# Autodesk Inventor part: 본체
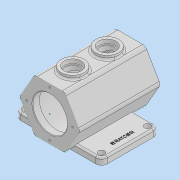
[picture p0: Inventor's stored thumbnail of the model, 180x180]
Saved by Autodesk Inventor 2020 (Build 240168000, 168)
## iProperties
Created: 2021-06
Part Number: 본체
Material: 일반
Document SubType Name: Modeling
Designer: MIRAE
Density: 1 g/cm^3
Appearance: 기본값
Author: MIRAE
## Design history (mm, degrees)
sketch "스케치1" dims "d1" = 105
  geometry: L1 (-26.25, -45.466)-(-52.5, 0); L2 (-52.5, 0)-(-26.25, 45.466); L3 (-26.25, 45.466)-(26.25, 45.466); L4 (26.25, 45.466)-(52.5, 0); L5 (52.5, 0)-(26.25, -45.466); L6 (26.25, -45.466)-(-26.25, -45.466); 3 further points
  constraints: 12 end point, 2 coincident, 1 horizontal, 16 other
extrude "돌출1" new body sketch "스케치1" stored distance "d2" = 140; taper "d3" = 0 deg
sketch "스케치2"
  geometry: L1 (26.25, -45.466)-(52.5, 0) reference; L2 (52.5, 0)-(26.25, 45.466) reference; L3 (26.25, 45.466)-(-26.25, 45.466) reference; L4 (-26.25, 45.466)-(-52.5, 0) reference; L5 (-52.5, 0)-(-26.25, -45.466) reference; L6 (-26.25, -45.466)-(26.25, -45.466) reference; 1 further point
sketch "스케치3"
  geometry: L1 (70, 0)-(70, -45.466) reference; L2 (70, 0)-(70, 30); L3 (70, 45.466)-(70, 0) reference; L4 (70, 30)-(58, 30); L5 (58, 30)-(58, 37.5); L6 (58, 37.5)-(-58, 37.5); L7 (-58, 37.5)-(-58, 30); L8 (-58, 30)-(-70, 30); L9 (-70, 0)-(-70, 45.466) reference; L10 (-70, 30)-(-70, 0); L11 (70, 0)-(-70, 0) reference; L12 (-70, 0)-(70, 0)
  constraints: 16 end point, 4 perpendicular, 3 point on line, 1 collinear, 1 parallel
  dimensions: "d12" = 30 distance of L1.start L2.end; "d13" = 12 distance of L2.end L4.end; "d14" = 37.5 distance between parallel lines of L11 L6; "d15" = 12 distance of L7.end L8.end
revolve "회전2" sketch "스케치3" stored, may be unused: angle "d16" = 90 deg
node "작업 평면2"
sketch "스케치7"
  geometry: L1 (26.25, -70)-(-26.25, -70) reference; C1 r 20 at (0, -30); 1 further point
  constraints: 1 centre point
  dimensions: "d38" = 40 diameter of C1; "d39" = 40 distance from line of L1 C1.centre; "d40" = 0 horizontal distance of point (0, 0) C1.centre
extrude "돌출3" join sketch "스케치7" stored distance "d41" = 10; taper "d42" = 0 deg
sketch "스케치8"
  geometry: C1 r 20 at (0, 0) reference; 2 further points
  constraints: 1 coincident
hole "구멍3" sketch "스케치8" at (0, 0) diameter "d43" = 25; stored, may be unused: countersink angle "d47" = 90 deg, drill point angle "d49" = 0 deg; dims "d44" = 10, "d45" = 30, "d46" = 8, "d48" = 25
node "작업 평면3"
node "작업 평면4"
sketch "스케치9"
  geometry: L1 (52.5, -140)-(52.5, 0) reference; L2 (0, 0)-(52.5, 0) reference; L3 (0, -140)-(0, 0) reference; L4 (52.5, -140)-(0, -140) reference; 1 further point
sketch "스케치10"
  geometry: L1 (-75, 15)-(75, 15); L2 (75, 15)-(75, -85); L3 (75, -85)-(-75, -85); L4 (-75, -85)-(-75, 15); L5 (-52.5, 40)-(-26.25, 40) reference; L6 (-26.25, -100)-(-52.5, -100) reference; 1 further point
  constraints: 8 end point, 2 parallel, 1 horizontal, 1 perpendicular
  dimensions: "d55" = 150 distance of L1.start L1.end; "d56" = 75 distance from line of point (0, -30) L4; "d82" = 25 distance between parallel lines of L1 L5; "d83" = 15 distance between parallel lines of L6 L3
extrude "돌출4" join sketch "스케치10" distance "d59" = 12; taper "d60" = 0 deg
fillet "모깎기1" dims "d73" = 10
sketch "스케치12"
  geometry: C1 r 5.5 at (65, 5); C2 r 5.5 at (65, -75); C3 r 5.5 at (-65, -75); C4 r 5.5 at (-65, 5); A1 r 10 centre (65, 5) between (75, 5) and (65, 15) reference; A2 r 10 centre (65, -75) between (65, -85) and (75, -75) reference; A3 r 10 centre (-65, -75) between (-75, -75) and (-65, -85) reference; A4 r 10 centre (-65, 5) between (-65, 15) and (-75, 5) reference; 1 further point
  constraints: 4 centre point, 4 coincident
  dimensions: "d74" = 11 diameter of C1; "d75" = 11 diameter of C2; "d76" = 11 diameter of C3; "d77" = 11 diameter of C4
extrude "돌출5" cut sketch "스케치12" distance "d78" = 12; taper "d79" = 0 deg
fillet "모깎기2" dims "d80" = 8
sketch "스케치13"
  geometry: L1 (75, -75)-(75, 5) reference; L2 (65, 15)-(30.387, 15) reference; 2 further points
  constraints: 1 other
  dimensions: "d84" = 14 distance from line of point (61, -35) L1; "d85" = 50 distance from line of L2 point (61, -35)
fillet "모깎기3" dims "d86" = 3
fillet "모깎기4" dims "d87" = 5
feature "엠보싱1" dims "d1" = 105, "d88" = 0.5, "d89" = 0
sketch "스케치14" dims "d92" = 80
  geometry: L1 (0, 0)-(50.358, -50.358); L2 (0, 0)-(0, -63.813); C1 r 30 at (0, 0) reference; 2 further points
  constraints: 4 end point, 1 coincident, 1 point on line, 1 vertical, 3 other
  dimensions: "d91" = 45 deg angle of L1 L2
hole "구멍5" sketch "스케치14" at (28.284, -28.284) diameter "d93" = 3.242; stored, may be unused: countersink angle "d97" = 90 deg, drill point angle "d99" = 118 deg; dims "d94" = 8, "d95" = 30, "d96" = 8, "d98" = 10
sketch "스케치15" dims "d103" = 80
  geometry: L1 (0, 0)-(0, 90.933); C1 r 30 at (0, 0) reference; C2 r 30 at (0, 0) reference; 2 further points
  constraints: 2 end point, 1 coincident, 1 point on line, 1 vertical, 1 vertical alignment, 2 other
hole "구멍6" sketch "스케치15" at (0, 40) diameter "d104" = 3.242; stored, may be unused: countersink angle "d108" = 90 deg, drill point angle "d110" = 118 deg; dims "d105" = 8, "d106" = 30, "d107" = 8, "d109" = 10
chamfer "모따기1" distance "d114" = 1; stored, may be unused: second distance "d115" = 2, angle "d116" = 45 deg
chamfer "모따기2" distance "d117" = 1; stored, may be unused: second distance "d118" = 2, angle "d119" = 45 deg
node "솔리드1"
pattern_linear "직사각형 패턴1" dims "d52" = 60
pattern_circular "원형 패턴2" dims angle "d101" = 360 deg
pattern_circular "원형 패턴3" dims angle "d112" = 360 deg
feature "A9D066F2-1C7D-4E18-AEED-F7BC21143FA4" dims "d43" = 25, "d44" = 10, "d45" = 30, "d46" = 8, "d47" = 90 deg, "d48" = 25, "d49" = 0
other parameters: "d5" = 12, "d6" = 12, "d37" = 52.2, "d53" = -102.5, "d54" = -102.5
